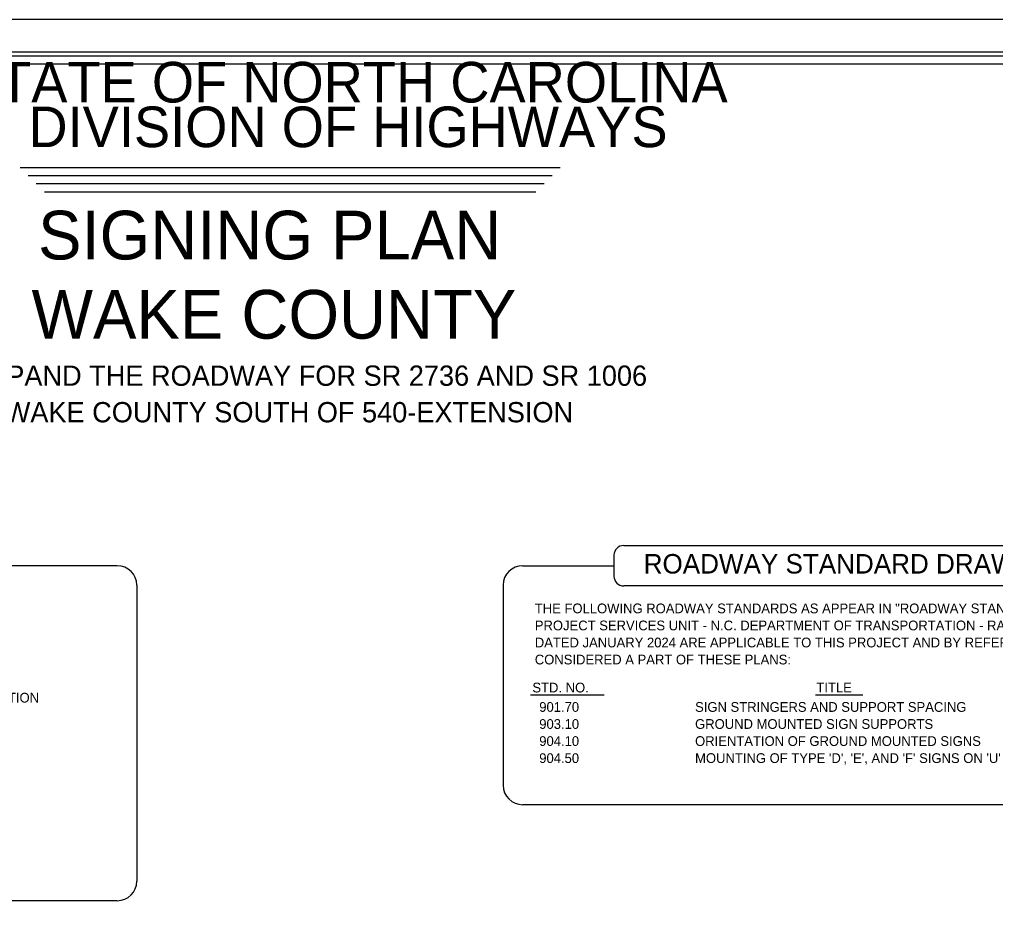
# Model space of a CAD drawing. Extents: x 2046816 to 2049224, y 578750 to 586986.
# Drawn here: x 2048289 to 2048890, y 586432 to 586986 of the extents above; entities that cross this region are included whole.
import ezdxf

# ---------------------------------------------------------------- set-up
doc = ezdxf.new("R2010")
doc.units = 0
for name, color, linetype in [('Default', 7, 'Continuous'), ('Sheet Data Field CELL', 7, 'Continuous'), ('Sheet Plot Border Inside CELL', 7, 'Continuous'), ('Sheet Plot Border Outside CELL', 7, 'Continuous'), ('Sheet Title CELL', 7, 'Continuous')]:
    doc.layers.add(name, color=color, linetype=linetype)

msp = doc.modelspace()

# ---------------------------------------------------------------- linework, layer by layer
at = {"layer": 'Default'}
for p, q in [((2048604.09, 586570.13), (2048649.47, 586570.13)), ((2048779.54, 586570.13), (2048808.7, 586570.13))]:
    msp.add_line(p, q, dxfattribs=at)
at = {"layer": 'Sheet Plot Border Inside CELL'}
msp.add_lwpolyline([(2047553.67, 585910.81), (2049219.66, 585910.81), (2049219.66, 586965.81), (2047553.67, 586965.81)], close=True, dxfattribs=at)
at = {"layer": 'Sheet Plot Border Outside CELL'}
msp.add_lwpolyline([(2049224.17, 586985.81), (2047540.67, 586985.81), (2047540.67, 585890.81), (2049224.17, 585890.81)], close=True, dxfattribs=at)
at = {"layer": 'Sheet Title CELL'}
for p, q in [((2048289.56, 586894.76), (2048622.31, 586894.78)), ((2048294.56, 586889.78), (2048617.31, 586889.76)), ((2048299.56, 586884.76), (2048612.31, 586884.78)), ((2048304.56, 586879.76), (2048607.31, 586879.78)), ((2048661.4, 586661.97), (2048970.14, 586661.97)), ((2048655.4, 586655.97), (2048655.4, 586643.11)), ((2048349.44, 586649.54), (2048243.28, 586649.54)), ((2048599.13, 586649.54), (2048655.4, 586649.54)), ((2048361.44, 586637.54), (2048361.44, 586455.31)), ((2048587.13, 586637.54), (2048587.13, 586514.42)), ((2048970.14, 586637.11), (2048661.4, 586637.11)), ((2049032.41, 586502.42), (2048599.13, 586502.42)), ((2048349.44, 586443.31), (2047916.15, 586443.31))]:
    msp.add_line(p, q, dxfattribs=at)
for points in [[(2049192.16, 586963.31), (2047722.16, 586963.33)], [(2049192.16, 586958.31), (2047772.16, 586958.31)]]:
    msp.add_lwpolyline(points, dxfattribs=at)
for centre, radius, start, end in [((2048661.4, 586655.97), 6, 90, 180), ((2048349.44, 586637.54), 12, 360, 90), ((2048599.13, 586637.54), 12, 90, 180), ((2048661.4, 586643.11), 6, 180, 270), ((2048599.13, 586514.42), 12, 180, 270), ((2048349.44, 586455.31), 12, 270, 0)]:
    msp.add_arc(centre, radius, start, end, dxfattribs=at)

# ---------------------------------------------------------------- texts
at = {"layer": 'Default'}
for s, height, p in [('ROADWAY STANDARD DRAWING', 12, (2048673.71, 586644.72)), ('THE FOLLOWING ROADWAY STANDARDS AS APPEAR IN "ROADWAY STANDARD DRAWINGS" - ', 6, (2048606.64, 586620.26)), ('PROJECT SERVICES UNIT - N.C. DEPARTMENT OF TRANSPORTATION - RALEIGH, N.C.,', 6, (2048606.64, 586609.76)), ('DATED JANUARY 2024 ARE APPLICABLE TO THIS PROJECT AND BY REFERENCE HEREBY ARE', 6, (2048606.64, 586599.26)), ('CONSIDERED A PART OF THESE PLANS:', 6, (2048606.64, 586588.77)), ('WHEN EXISTING SIGNS ARE REMOVED AND INSTALLED ON NEW SUPPORTS, THE RE-ERECTION', 6, (2047923.67, 586565.28)), ('901.70', 6, (2048609.38, 586559.58)), ('SIGN STRINGERS AND SUPPORT SPACING', 6, (2048705.38, 586559.58)), ('903.10', 6, (2048609.38, 586549.08)), ('GROUND MOUNTED SIGN SUPPORTS', 6, (2048705.38, 586549.08)), ('904.10', 6, (2048609.38, 586538.58)), ('ORIENTATION OF GROUND MOUNTED SIGNS', 6, (2048705.38, 586538.58)), ('904.50', 6, (2048609.38, 586528.08)), ("MOUNTING OF TYPE 'D', 'E', AND 'F' SIGNS ON 'U' CHANNEL SUPPORTS", 6, (2048705.38, 586528.08))]:
    msp.add_text(s, height=height, dxfattribs=at).set_placement(p)
for s, p in [('STD. NO.', (2048605.14, 586571.52)), ('TITLE', (2048780.11, 586571.52))]:
    msp.add_text(s, height=6, rotation=360, dxfattribs=at).set_placement(p)
at = {"layer": 'Sheet Data Field CELL'}
for s, p in [('SIGNING PLAN', (2048300.63, 586838.08)), ('WAKE COUNTY', (2048296.6, 586789.33))]:
    msp.add_text(s, height=30, dxfattribs=at).set_placement(p)
for s, p in [('EXPAND THE ROADWAY FOR SR 2736 AND SR 1006', (2048258.75, 586760.3)), ('IN WAKE COUNTY SOUTH OF 540-EXTENSION', (2048258.75, 586737.8))]:
    msp.add_text(s, height=12.5001, rotation=360, dxfattribs=at).set_placement(p)
at = {"layer": 'Sheet Title CELL'}
for s, p in [('STATE OF NORTH CAROLINA', (2048253.72, 586934.73)), ('DIVISION OF HIGHWAYS', (2048294.67, 586907.23))]:
    msp.add_text(s, height=24.9999, dxfattribs=at).set_placement(p)

doc.saveas('drawing.dxf')
